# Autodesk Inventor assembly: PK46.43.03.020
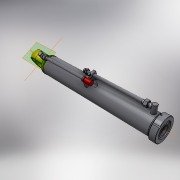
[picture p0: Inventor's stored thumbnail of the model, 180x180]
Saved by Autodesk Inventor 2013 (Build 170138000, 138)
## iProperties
Shininess: 64.0
Length Units: 11269
Angle Units: 11279
Time Units: 11290
Mass Units: 11283
Length Display Precision: 3
Angle Display Precision: 2
Compacted: True
Created: 2004-11
Part Number: PK46.43.03.020
Document SubType Name: Assembly
Designer: ELarisa
Manufacturer: Standard
Standards Organization: Custom
Density: 0.0
Volumn: 0.0
Area: 0.0
PropertySet Name: Model Information
Control State: 0
Master: False
Checked Out: False
Author: ELarisa
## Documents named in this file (13)
- C:\Product Design Suite 2013 Test Drive\Dynamic Simulation\Workspace\Assy, Chassis, Front\PK46.43.03.020.iam
- C:\Product Design Suite 2013 Test Drive\Dynamic Simulation\Workspace\Assy, Chassis, Front\PK46.43.01.002.ipt
- C:\Product Design Suite 2013 Test Drive\Dynamic Simulation\Workspace\Assy, Chassis, Front\PK46.43.01.007.ipt
- C:\Product Design Suite 2013 Test Drive\Dynamic Simulation\Workspace\Assy, Chassis, Front\PK46.43.01.050.iam
- C:\Product Design Suite 2013 Test Drive\Dynamic Simulation\Workspace\Assy, Chassis, Front\PK46.43.01.030.iam
- C:\Product Design Suite 2013 Test Drive\Dynamic Simulation\Workspace\Assy, Chassis, Front\PK46.43.01.006.ipt
- C:\Product Design Suite 2013 Test Drive\Dynamic Simulation\Workspace\Assy, Chassis, Front\PK46.43.01.040.iam
- C:\Product Design Suite 2013 Test Drive\Dynamic Simulation\Workspace\Assy, Chassis, Front\PK46.43.01.015.ipt
- C:\Product Design Suite 2013 Test Drive\Dynamic Simulation\Workspace\Assy, Chassis, Front\PK46.43.01.016.ipt
- C:\Product Design Suite 2013 Test Drive\Dynamic Simulation\Workspace\Assy, Chassis, Front\PK46.43.01.004.ipt
- C:\Product Design Suite 2013 Test Drive\Dynamic Simulation\Workspace\Assy, Chassis, Front\PK46.43.01.005.ipt
- C:\Product Design Suite 2013 Test Drive\Dynamic Simulation\Workspace\Assy, Chassis, Front\12.65G.019.ipt
- C:\Product Design Suite 2013 Test Drive\Dynamic Simulation\Workspace\Assy, Chassis, Front\M12-6gx45.58.019(S18).ipt
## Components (13 placed, 12 different names)
1. PK46.43.01.002:1 — Вставка:7, Вставка:9, Угол:7, Вставка:32, Insert:23
2. PK46.43.01.030:1 [sub-assembly] — Угол:7, Вставка:21, Угол:12, Угол:13, Insert:25
3. PK46.43.01.040:1 [sub-assembly] — Вставка:21
4. PK46.43.01.007:1 — Вставка:7, Insert:25
5. PK46.43.01.006:1 — Вставка:11
6. PK46.43.01.004:1 — Вставка:9, Вставка:10
7. PK46.43.01.005:1 — Вставка:10, Вставка:11, Угол:11
8. PK46.43.01.030:2 [sub-assembly] — Угол:11, Угол:12, Вставка:29, Insert:23
9. PK46.43.01.050:1 [sub-assembly] — Вставка:29
10. PK46.43.01.015:1 — Вставка:32, Угол:13, Заподлицо:1, Угол:14, Совмещение:2, Совмещение:3
11. PK46.43.01.016:1 — Заподлицо:1, Угол:14, Совмещение:2, Совмещение:3, Вставка:33
12. 12.65G.019:1 — Вставка:33, Вставка:34
13. M12-6gx45.58.019(S18):1 — Вставка:34
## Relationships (19: Insert 11, Angle 5, Mate 2, Flush 1)
- Вставка:7 [Insert]: PK46.43.01.002:1 ↔ PK46.43.01.007:1
- Вставка:9 [Insert]: PK46.43.01.002:1 ↔ PK46.43.01.004:1
- Вставка:10 [Insert]: PK46.43.01.004:1 ↔ PK46.43.01.005:1
- Вставка:11 [Insert]: PK46.43.01.006:1 ↔ PK46.43.01.005:1
- Угол:7 [Angle]: PK46.43.01.002:1 ↔ PK46.43.01.030:1
- Вставка:21 [Insert]: PK46.43.01.030:1 ↔ PK46.43.01.040:1
- Угол:11 [Angle]: PK46.43.01.005:1 ↔ PK46.43.01.030:2
- Угол:12 [Angle]: PK46.43.01.030:1 ↔ PK46.43.01.030:2
- Вставка:29 [Insert]: PK46.43.01.030:2 ↔ PK46.43.01.050:1
- Вставка:32 [Insert]: PK46.43.01.002:1 ↔ PK46.43.01.015:1
- Угол:13 [Angle]: PK46.43.01.030:1 ↔ PK46.43.01.015:1
- Заподлицо:1 [Flush]: PK46.43.01.015:1 ↔ PK46.43.01.016:1
- Угол:14 [Angle]: PK46.43.01.015:1 ↔ PK46.43.01.016:1
- Совмещение:2 [Mate]: PK46.43.01.015:1 ↔ PK46.43.01.016:1
- Совмещение:3 [Mate]: PK46.43.01.015:1 ↔ PK46.43.01.016:1
- Вставка:33 [Insert]: PK46.43.01.016:1 ↔ 12.65G.019:1
- Вставка:34 [Insert]: 12.65G.019:1 ↔ M12-6gx45.58.019(S18):1
- Insert:23: PK46.43.01.002:1 ↔ PK46.43.01.030:2
- Insert:25: PK46.43.01.030:1 ↔ PK46.43.01.007:1
